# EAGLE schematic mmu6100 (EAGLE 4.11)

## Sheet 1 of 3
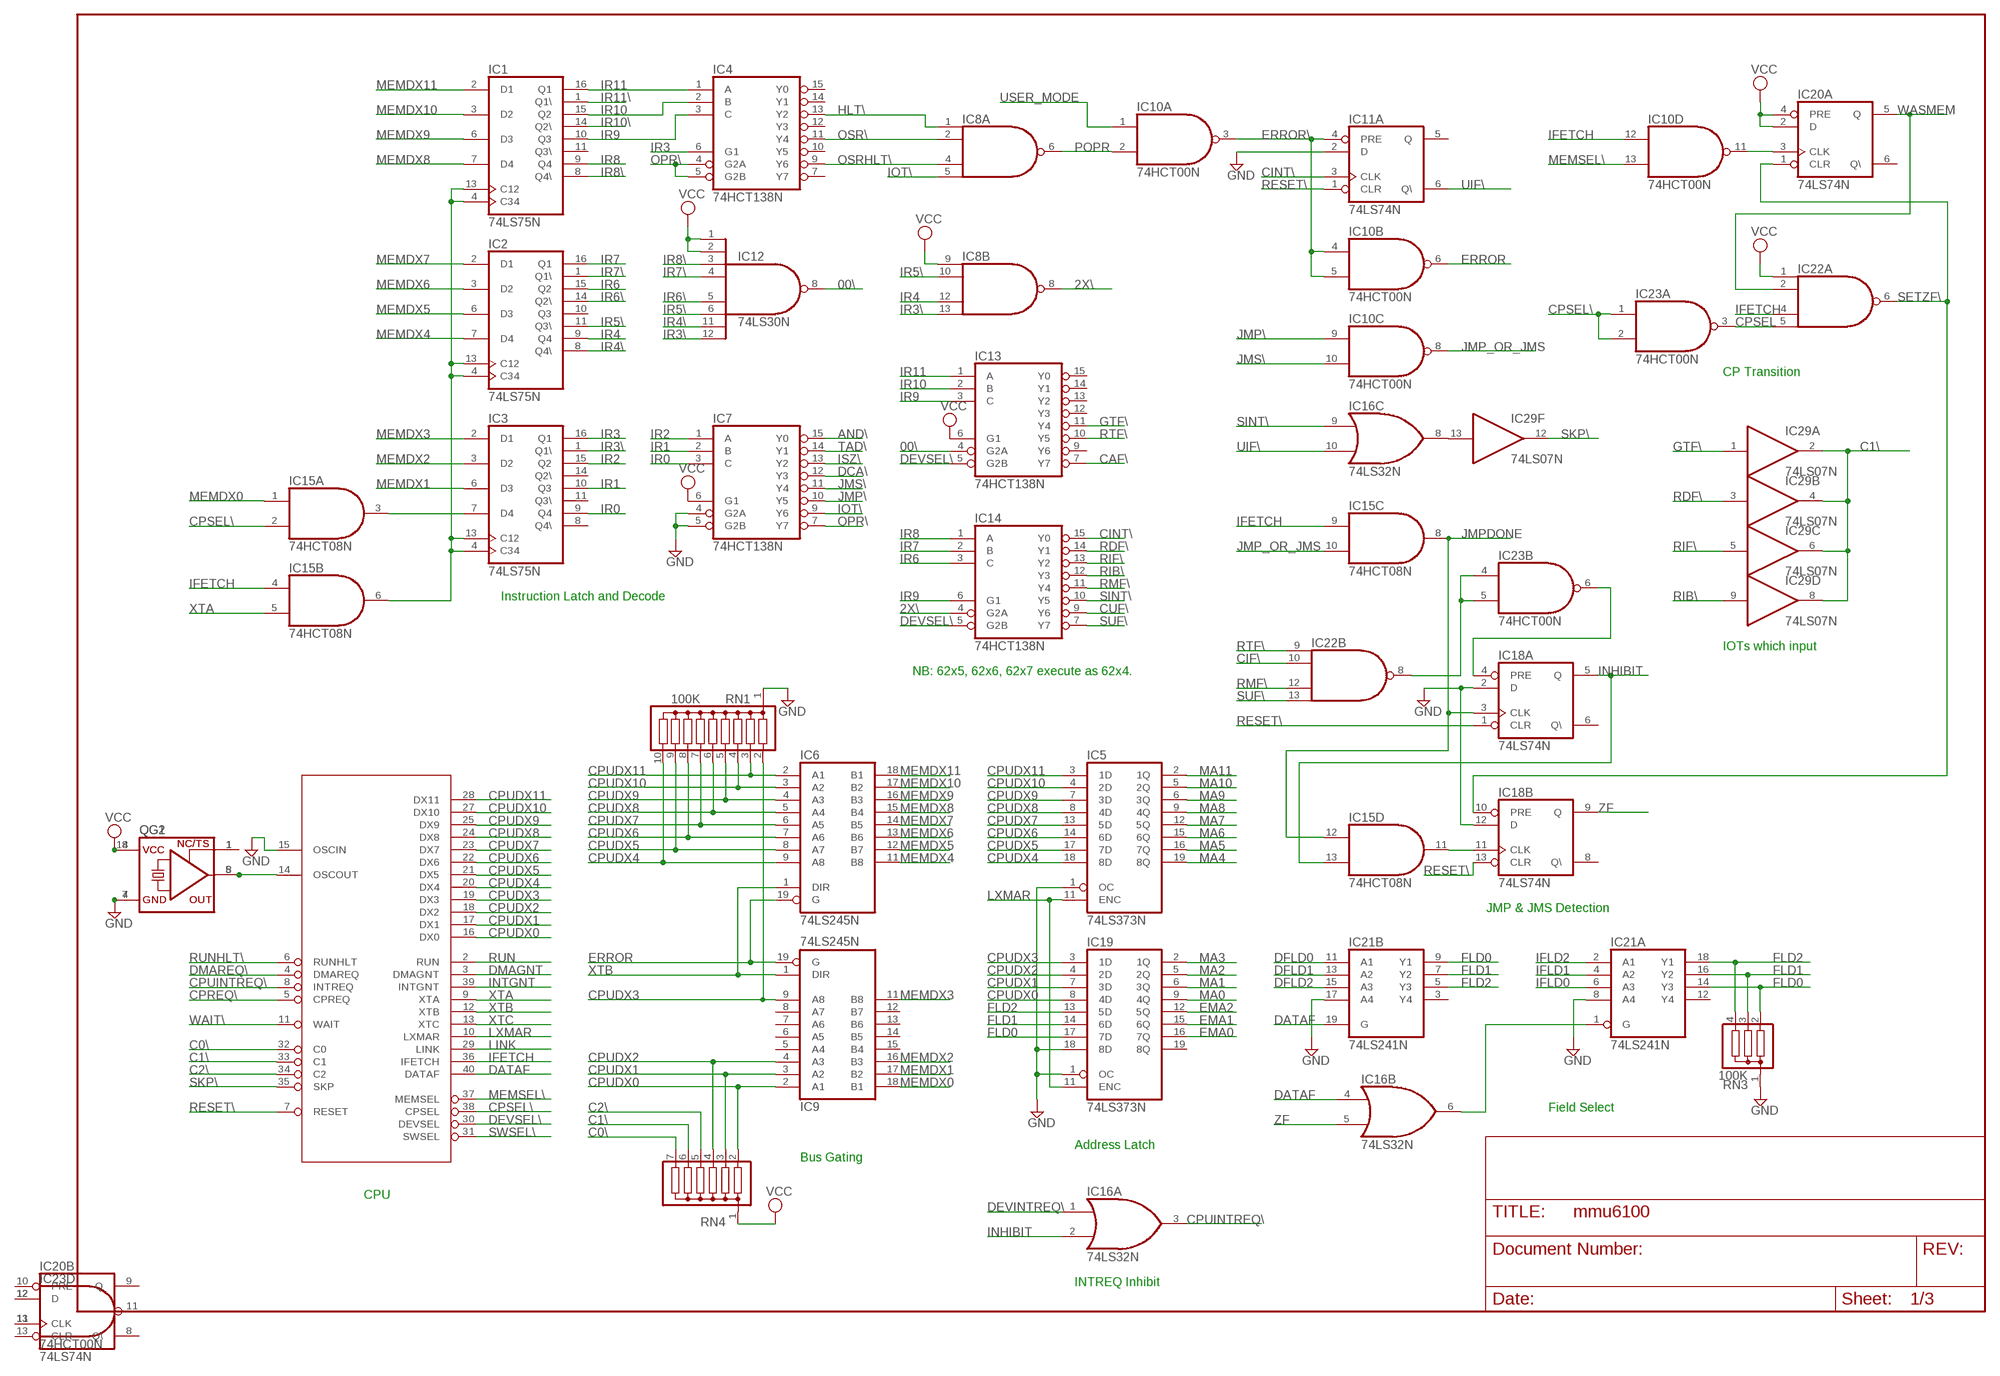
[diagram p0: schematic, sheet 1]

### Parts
CPU  IM6100  [DIL40]
IC1  74LS75N  [DIL16]
IC2  74LS75N  [DIL16]
IC3  74LS75N  [DIL16]
IC4  74HCT138N  [DIL16]
IC5  74LS373N  [DIL20]
IC6  74LS245N  [DIL20]
IC7  74HCT138N  [DIL16]
IC8  74LS20N  [DIL14]
IC9  74LS245N  [DIL20]
IC10  74HCT00N  [DIL14]
IC11  74LS74N  [DIL14]
IC12  74LS30N  [DIL14]
IC13  74HCT138N  [DIL16]
IC14  74HCT138N  [DIL16]
IC15  74HCT08N  [DIL14]
IC16  74LS32N  [DIL14]
IC18  74LS74N  [DIL14]
IC19  74LS373N  [DIL20]
IC20  74LS74N  [DIL14]
IC21  74LS241N  [DIL20]
IC22  74LS20N  [DIL14]
IC23  74HCT00N  [DIL14]
IC29  74LS07N  [DIL14]
QG1  XO-8  [DIL08S]
QG2  XO-14  [DIL14S]
RN1  100K  G09R  [SIL10]
RN3  100K  G03R  [SIL4]
RN4  G06R  [SIL7]

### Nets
00\: IC12.8(O) IC13.4(G2A)
2X\: IC8.8(B:O) IC14.4(G2A) ; also sheet 2
AND\: IC7.15(Y0) ; also sheet 3
C0\: CPU.32(C0) RN4.7 ; also sheet 3
C1\: CPU.33(C1) IC29.2(A:O) IC29.4(B:O) IC29.6(C:O) IC29.8(D:O) RN4.6 ; also sheet 3
C2\: CPU.34(C2) RN4.5 ; also sheet 3
CAF\: IC13.7(Y7) ; also sheet 2
CIF\: IC22.10(B:I1) ; also sheet 2
CINT\: IC11.3(A:CLK) IC14.15(Y0)
CPREQ\: CPU.5(CPREQ) ; also sheet 3
CPSEL: IC22.5(A:I3) IC23.3(A:O)
CPSEL\: CPU.38(CPSEL) IC15.2(A:I1) IC23.1(A:I0) IC23.2(A:I1)
CPUDX0: CPU.16(DX0) IC9.2(A1) IC19.8(4D) RN4.2 ; also sheet 2
CPUDX1: CPU.17(DX1) IC9.3(A2) IC19.7(3D) RN4.3 ; also sheet 2
CPUDX2: CPU.18(DX2) IC9.4(A3) IC19.4(2D) RN4.4 ; also sheet 2
CPUDX3: CPU.19(DX3) IC9.9(A8) IC19.3(1D) RN1.2 ; also sheet 2
CPUDX4: CPU.20(DX4) IC5.18(8D) IC6.9(A8) RN1.10 ; also sheet 2
CPUDX5: CPU.21(DX5) IC5.17(7D) IC6.8(A7) RN1.9 ; also sheet 2
CPUDX6: CPU.22(DX6) IC5.14(6D) IC6.7(A6) RN1.8 ; also sheet 2
CPUDX7: CPU.23(DX7) IC5.13(5D) IC6.6(A5) RN1.7 ; also sheet 2
CPUDX8: CPU.24(DX8) IC5.8(4D) IC6.5(A4) RN1.6 ; also sheet 2
CPUDX9: CPU.25(DX9) IC5.7(3D) IC6.4(A3) RN1.5 ; also sheet 2
CPUDX10: CPU.27(DX10) IC5.4(2D) IC6.3(A2) RN1.4 ; also sheet 2
CPUDX11: CPU.28(DX11) IC5.3(1D) IC6.2(A1) RN1.3 ; also sheet 2
CPUINTREQ\: CPU.8(INTREQ) IC16.3(A:O)
CUF\: IC14.9(Y6) ; also sheet 2
DATAF: CPU.40(DATAF) IC16.4(B:I0) IC21.19(B:G)
DCA\: IC7.12(Y3) ; also sheet 3
DEVINTREQ\: IC16.1(A:I0) ; also sheet 2,3
DEVSEL\: CPU.30(DEVSEL) IC13.5(G2B) IC14.5(G2B) ; also sheet 3
DFLD0: IC21.11(B:A1) ; also sheet 2
DFLD1: IC21.13(B:A2) ; also sheet 2
DFLD2: IC21.15(B:A3) ; also sheet 2
DMAGNT: CPU.3(DMAGNT) ; also sheet 3
DMAREQ\: CPU.4(DMAREQ) ; also sheet 3
EMA0: IC19.16(7Q) ; also sheet 3
EMA1: IC19.15(6Q) ; also sheet 3
EMA2: IC19.12(5Q) ; also sheet 3
ERROR: IC6.19(G) IC9.19(G) IC10.6(B:O)
ERROR\: IC10.3(A:O) IC10.4(B:I0) IC10.5(B:I1) IC11.4(A:PRE)
FLD0: IC19.17(7D) IC21.9(B:Y1) IC21.14(A:Y3) RN3.2
FLD1: IC19.14(6D) IC21.7(B:Y2) IC21.16(A:Y2) RN3.3
FLD2: IC19.13(5D) IC21.5(B:Y3) IC21.18(A:Y1) RN3.4
GND: CPU.15(OSCIN) IC5.1(OC) IC7.4(G2A) IC7.5(G2B) IC11.2(A:D) IC18.2(A:D) IC18.12(B:D) IC19.1(OC) IC19.18(8D) IC21.8(A:A4) IC21.17(B:A4) QG1.4(GND) QG2.7(GND) RN1.1 RN3.1 ; also sheet 2,3
GTF\: IC13.11(Y4) IC29.1(A:I) ; also sheet 2
HLT\: IC4.13(Y2) IC8.1(A:I0)
IFETCH: CPU.36(IFETCH) IC10.12(D:I0) IC15.4(B:I0) IC15.9(C:I0) IC22.4(A:I2)
IFLD0: IC21.6(A:A3) ; also sheet 2
IFLD1: IC21.4(A:A2) ; also sheet 2
IFLD2: IC21.2(A:A1) ; also sheet 2
INHIBIT: IC15.13(D:I1) IC16.2(A:I1) IC18.5(A:Q) ; also sheet 2
INTGNT: CPU.39(INTGNT) ; also sheet 2,3
IOT\: IC7.9(Y6) IC8.5(A:I3) ; also sheet 2
IR0: IC3.9(Q4) IC7.3(C)
IR1: IC3.10(Q3) IC7.2(B)
IR2: IC3.15(Q2) IC7.1(A)
IR3: IC3.16(Q1) IC4.6(G1)
IR3\: IC3.1(Q1\) IC8.13(B:I3) IC12.12(I7)
IR4: IC2.9(Q4) IC8.12(B:I2)
IR4\: IC2.8(Q4\) IC12.11(I6)
IR5\: IC2.11(Q3\) IC8.10(B:I1) IC12.6(I5)
IR6: IC2.15(Q2) IC14.3(C) ; also sheet 2
IR6\: IC2.14(Q2\) IC12.5(I4)
IR7: IC2.16(Q1) IC14.2(B) ; also sheet 2
IR7\: IC2.1(Q1\) IC12.4(I3)
IR8: IC1.9(Q4) IC14.1(A) ; also sheet 2
IR8\: IC1.8(Q4\) IC12.3(I2)
IR9: IC1.10(Q3) IC4.3(C) IC13.3(C) IC14.6(G1) ; also sheet 2
IR10: IC1.15(Q2) IC4.2(B) IC13.2(B)
IR10\: IC1.14(Q2\) ; also sheet 2
IR11: IC1.16(Q1) IC4.1(A) IC13.1(A)
IR11\: IC1.1(Q1\) ; also sheet 2
ISZ\: IC7.13(Y2) ; also sheet 3
JMP\: IC7.10(Y5) IC10.9(C:I0)
JMP_OR_JMS: IC10.8(C:O) IC15.10(C:I1)
JMPDONE: IC15.8(C:O) IC15.12(D:I0) IC18.3(A:CLK) ; also sheet 2
JMS\: IC7.11(Y4) IC10.10(C:I1)
LINK: CPU.29(LINK) ; also sheet 3
LXMAR: CPU.10(LXMAR) IC5.11(ENC) IC19.11(ENC) ; also sheet 2,3
MA0: IC19.9(4Q) ; also sheet 3
MA1: IC19.6(3Q) ; also sheet 3
MA2: IC19.5(2Q) ; also sheet 3
MA3: IC19.2(1Q) ; also sheet 3
MA4: IC5.19(8Q) ; also sheet 3
MA5: IC5.16(7Q) ; also sheet 3
MA6: IC5.15(6Q) ; also sheet 3
MA7: IC5.12(5Q) ; also sheet 3
MA8: IC5.9(4Q) ; also sheet 3
MA9: IC5.6(3Q) ; also sheet 3
MA10: IC5.5(2Q) ; also sheet 3
MA11: IC5.2(1Q) ; also sheet 3
MEMDX0: IC9.18(B1) IC15.1(A:I0) ; also sheet 3
MEMDX1: IC3.6(D3) IC9.17(B2) ; also sheet 3
MEMDX2: IC3.3(D2) IC9.16(B3) ; also sheet 3
MEMDX3: IC3.2(D1) IC9.11(B8) ; also sheet 3
MEMDX4: IC2.7(D4) IC6.11(B8) ; also sheet 3
MEMDX5: IC2.6(D3) IC6.12(B7) ; also sheet 3
MEMDX6: IC2.3(D2) IC6.13(B6) ; also sheet 3
MEMDX7: IC2.2(D1) IC6.14(B5) ; also sheet 3
MEMDX8: IC1.7(D4) IC6.15(B4) ; also sheet 3
MEMDX9: IC1.6(D3) IC6.16(B3) ; also sheet 3
MEMDX10: IC1.3(D2) IC6.17(B2) ; also sheet 3
MEMDX11: IC1.2(D1) IC6.18(B1) ; also sheet 3
MEMSEL\: CPU.37(MEMSEL) IC10.13(D:I1) ; also sheet 3
N$2: QG1.1(TS) QG2.1(TS)
N$3: IC1.4(C34) IC1.13(C12) IC2.4(C34) IC2.13(C12) IC3.4(C34) IC3.13(C12) IC15.6(B:O)
N$5: IC15.11(D:O) IC18.11(B:CLK)
N$6: IC10.11(D:O) IC20.3(A:CLK)
N$8: IC16.6(B:O) IC21.1(A:G)
N$15: IC3.7(D4) IC15.3(A:O)
N$23: IC16.8(C:O) IC29.13(F:I)
N$29: IC22.8(B:O) IC23.4(B:I0) IC23.5(B:I1)
N$30: IC18.4(A:PRE) IC23.6(B:O)
OPR\: IC4.4(G2A) IC4.5(G2B) IC7.7(Y7)
OSCOUT: CPU.14(OSCOUT) QG1.5(OUT) QG2.8(OUT)
OSR\: IC4.11(Y4) IC8.2(A:I1)
OSRHLT\: IC4.9(Y6) IC8.4(A:I2)
POPR: IC8.6(A:O) IC10.2(A:I1)
RDF\: IC14.14(Y1) IC29.3(B:I) ; also sheet 2
RESET\: CPU.7(RESET) IC11.1(A:CLR) IC18.1(A:CLR) IC18.13(B:CLR) ; also sheet 2,3
RIB\: IC14.12(Y3) IC29.9(D:I) ; also sheet 2
RIF\: IC14.13(Y2) IC29.5(C:I) ; also sheet 2
RMF\: IC14.11(Y4) IC22.12(B:I2) ; also sheet 2
RTF\: IC13.10(Y5) IC22.9(B:I0) ; also sheet 2
RUN: CPU.2(RUN) ; also sheet 3
RUNHLT\: CPU.6(RUNHLT) ; also sheet 3
SETZF\: IC18.10(B:PRE) IC20.1(A:CLR) IC22.6(A:O)
SINT\: IC14.10(Y5) IC16.9(C:I0)
SKP\: CPU.35(SKP) IC29.12(F:O) ; also sheet 3
SUF\: IC14.7(Y7) IC22.13(B:I3) ; also sheet 2
SWSEL\: CPU.31(SWSEL) ; also sheet 3
TAD\: IC7.14(Y1) ; also sheet 3
UIF\: IC11.6(A:Q\) IC16.10(C:I1)
USER_MODE: IC10.1(A:I0) ; also sheet 2
VCC: IC7.6(G1) IC8.9(B:I0) IC12.1(I0) IC12.2(I1) IC13.6(G1) IC20.2(A:D) IC20.4(A:PRE) IC22.1(A:I0) QG1.8(VCC) QG2.14(VCC) RN4.1 ; also sheet 2,3
WAIT\: CPU.11(WAIT) ; also sheet 3
WASMEM: IC20.5(A:Q) IC22.2(A:I1)
XTA: CPU.9(XTA) IC15.5(B:I1) ; also sheet 2,3
XTB: CPU.12(XTB) IC6.1(DIR) IC9.1(DIR) ; also sheet 2,3
XTC: CPU.13(XTC) ; also sheet 3
ZF: IC16.5(B:I1) IC18.9(B:Q)
Unconnected: IC1.11(Q3\) IC2.10(Q3) IC3.8(Q4\) IC3.11(Q3\) IC3.14(Q2\) IC4.7(Y7) IC4.10(Y5) IC4.12(Y3) IC4.14(Y1) IC4.15(Y0) IC9.5(A4) IC9.6(A5) IC9.7(A6) IC9.8(A7) IC9.12(B7) IC9.13(B6) IC9.14(B5) IC9.15(B4) IC13.9(Y6) IC13.12(Y3) IC13.13(Y2) IC13.14(Y1) IC13.15(Y0) IC18.6(A:Q\) IC18.8(B:Q\) IC19.19(8Q) IC21.3(B:Y4) IC21.12(A:Y4)

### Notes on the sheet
- CP Transition
- Instruction Latch and Decode
- IOTs which input
- NB: 62x5, 62x6, 62x7 execute as 62x4.
- JMP & JMS Detection
- Field Select
- Address Latch
- Bus Gating
- CPU
- INTREQ Inhibit

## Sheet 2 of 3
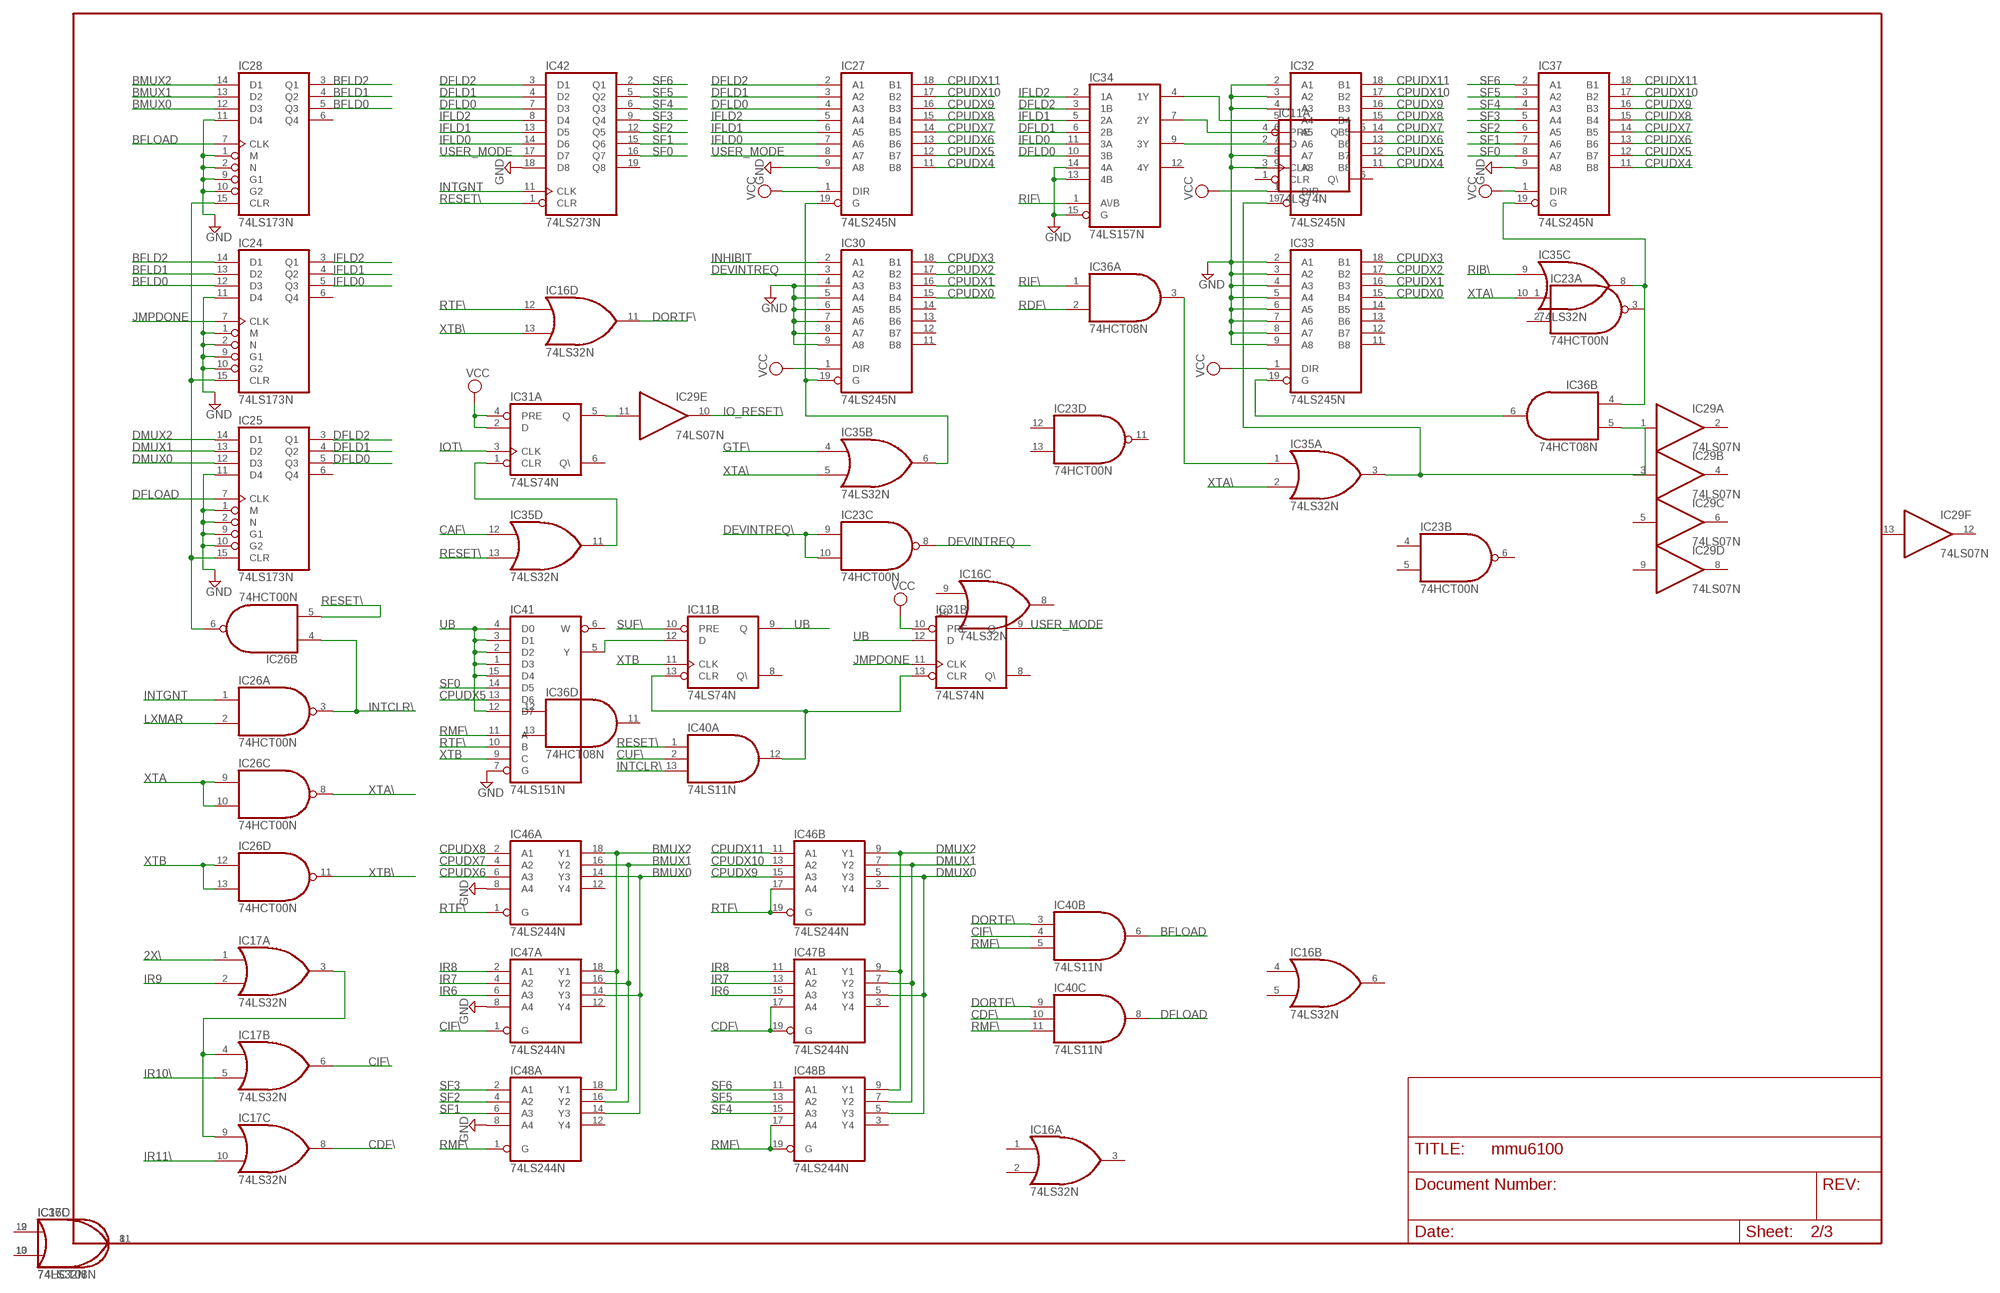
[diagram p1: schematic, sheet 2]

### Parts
IC17  74LS32N  [DIL14]
IC24  74LS173N  [DIL16]
IC25  74LS173N  [DIL16]
IC26  74HCT00N  [DIL14]
IC27  74LS245N  [DIL20]
IC28  74LS173N  [DIL16]
IC30  74LS245N  [DIL20]
IC31  74LS74N  [DIL14]
IC32  74LS245N  [DIL20]
IC33  74LS245N  [DIL20]
IC34  74LS157N  [DIL16]
IC35  74LS32N  [DIL14]
IC36  74HCT08N  [DIL14]
IC37  74LS245N  [DIL20]
IC40  74LS11N  [DIL14]
IC41  74LS151N  [DIL16]
IC42  74LS273N  [DIL20]
IC46  74LS244N  [DIL20]
IC47  74LS244N  [DIL20]
IC48  74LS244N  [DIL20]

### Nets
2X\: IC17.1(A:I0) ; also sheet 1
BFLD0: IC24.12(D3) IC28.5(Q3)
BFLD1: IC24.13(D2) IC28.4(Q2)
BFLD2: IC24.14(D1) IC28.3(Q1)
BFLOAD: IC28.7(CLK) IC40.6(B:O)
BMUX0: IC28.12(D3) IC46.14(A:Y3) IC47.14(A:Y3) IC48.14(A:Y3)
BMUX1: IC28.13(D2) IC46.16(A:Y2) IC47.16(A:Y2) IC48.16(A:Y2)
BMUX2: IC28.14(D1) IC46.18(A:Y1) IC47.18(A:Y1) IC48.18(A:Y1)
CAF\: IC35.12(D:I0) ; also sheet 1
CDF\: IC17.8(C:O) IC40.10(C:I1) IC47.17(B:A4) IC47.19(B:G)
CIF\: IC17.6(B:O) IC40.4(B:I1) IC47.1(A:G) ; also sheet 1
CPUDX0: IC30.15(B4) IC33.15(B4) ; also sheet 1
CPUDX1: IC30.16(B3) IC33.16(B3) ; also sheet 1
CPUDX2: IC30.17(B2) IC33.17(B2) ; also sheet 1
CPUDX3: IC30.18(B1) IC33.18(B1) ; also sheet 1
CPUDX4: IC27.11(B8) IC32.11(B8) IC37.11(B8) ; also sheet 1
CPUDX5: IC27.12(B7) IC32.12(B7) IC37.12(B7) IC41.13(D6) ; also sheet 1
CPUDX6: IC27.13(B6) IC32.13(B6) IC37.13(B6) IC46.6(A:A3) ; also sheet 1
CPUDX7: IC27.14(B5) IC32.14(B5) IC37.14(B5) IC46.4(A:A2) ; also sheet 1
CPUDX8: IC27.15(B4) IC32.15(B4) IC37.15(B4) IC46.2(A:A1) ; also sheet 1
CPUDX9: IC27.16(B3) IC32.16(B3) IC37.16(B3) IC46.15(B:A3) ; also sheet 1
CPUDX10: IC27.17(B2) IC32.17(B2) IC37.17(B2) IC46.13(B:A2) ; also sheet 1
CPUDX11: IC27.18(B1) IC32.18(B1) IC37.18(B1) IC46.11(B:A1) ; also sheet 1
CUF\: IC40.2(A:I1) ; also sheet 1
DEVINTREQ: IC23.8(C:O) IC30.3(A2)
DEVINTREQ\: IC23.9(C:I0) IC23.10(C:I1) ; also sheet 1,3
DFLD0: IC25.5(Q3) IC27.4(A3) IC34.10(3B) IC42.7(D3) ; also sheet 1
DFLD1: IC25.4(Q2) IC27.3(A2) IC34.6(2B) IC42.4(D2) ; also sheet 1
DFLD2: IC25.3(Q1) IC27.2(A1) IC34.3(1B) IC42.3(D1) ; also sheet 1
DFLOAD: IC25.7(CLK) IC40.8(C:O)
DMUX0: IC25.12(D3) IC46.5(B:Y3) IC47.5(B:Y3) IC48.5(B:Y3)
DMUX1: IC25.13(D2) IC46.7(B:Y2) IC47.7(B:Y2) IC48.7(B:Y2)
DMUX2: IC25.14(D1) IC46.9(B:Y1) IC47.9(B:Y1) IC48.9(B:Y1)
DORTF\: IC16.11(D:O) IC40.3(B:I0) IC40.9(C:I0)
GND: IC24.1(M) IC24.2(N) IC24.9(G1) IC24.10(G2) IC24.11(D4) IC25.1(M) IC25.2(N) IC25.9(G1) IC25.10(G2) IC25.11(D4) IC27.9(A8) IC28.1(M) IC28.2(N) IC28.9(G1) IC28.10(G2) IC28.11(D4) IC30.4(A3) IC30.5(A4) IC30.6(A5) IC30.7(A6) IC30.8(A7) IC30.9(A8) IC32.2(A1) IC32.3(A2) IC32.4(A3) IC32.8(A7) IC32.9(A8) IC33.2(A1) IC33.3(A2) IC33.4(A3) IC33.5(A4) IC33.6(A5) IC33.7(A6) IC33.8(A7) IC33.9(A8) IC34.13(4B) IC34.14(4A) IC34.15(G) IC37.9(A8) IC41.7(G) IC42.18(D8) IC46.8(A:A4) IC47.8(A:A4) IC48.8(A:A4) ; also sheet 1,3
GTF\: IC35.4(B:I0) ; also sheet 1
IFLD0: IC24.5(Q3) IC27.7(A6) IC34.11(3A) IC42.14(D6) ; also sheet 1
IFLD1: IC24.4(Q2) IC27.6(A5) IC34.5(2A) IC42.13(D5) ; also sheet 1
IFLD2: IC24.3(Q1) IC27.5(A4) IC34.2(1A) IC42.8(D4) ; also sheet 1
INHIBIT: IC30.2(A1) ; also sheet 1
INTCLR: IC24.15(CLR) IC25.15(CLR) IC26.6(B:O) IC28.15(CLR)
INTCLR\: IC26.3(A:O) IC26.4(B:I0) IC40.13(A:I2)
INTGNT: IC26.1(A:I0) IC42.11(CLK) ; also sheet 1,3
IO_RESET\: IC29.10(E:O) ; also sheet 3
IOT\: IC31.3(A:CLK) ; also sheet 1
IR6: IC47.6(A:A3) IC47.15(B:A3) ; also sheet 1
IR7: IC47.4(A:A2) IC47.13(B:A2) ; also sheet 1
IR8: IC47.2(A:A1) IC47.11(B:A1) ; also sheet 1
IR9: IC17.2(A:I1) ; also sheet 1
IR10\: IC17.5(B:I1) ; also sheet 1
IR11\: IC17.10(C:I1) ; also sheet 1
JMPDONE: IC24.7(CLK) IC31.11(B:CLK) ; also sheet 1
LXMAR: IC26.2(A:I1) ; also sheet 1,3
N$4: IC27.19(G) IC30.19(G) IC35.6(B:O)
N$7: IC29.11(E:I) IC31.5(A:Q)
N$9: IC32.19(G) IC35.3(A:O) IC36.5(B:I1)
N$12: IC35.8(C:O) IC36.4(B:I0) IC37.19(G)
N$14: IC32.5(A4) IC34.4(1Y)
N$19: IC32.6(A5) IC34.7(2Y)
N$22: IC32.7(A6) IC34.9(3Y)
N$24: IC35.1(A:I0) IC36.3(A:O)
N$25: IC33.19(G) IC36.6(B:O)
N$26: IC11.13(B:CLR) IC31.13(B:CLR) IC40.12(A:O)
N$27: IC11.12(B:D) IC41.5(Y)
N$28: IC31.1(A:CLR) IC35.11(D:O)
N$33: IC17.3(A:O) IC17.4(B:I0) IC17.9(C:I0)
RDF\: IC36.2(A:I1) ; also sheet 1
RESET\: IC26.5(B:I1) IC35.13(D:I1) IC40.1(A:I0) IC42.1(CLR) ; also sheet 1,3
RIB\: IC35.9(C:I0) ; also sheet 1
RIF\: IC34.1(A\/B) IC36.1(A:I0) ; also sheet 1
RMF\: IC40.5(B:I2) IC40.11(C:I2) IC41.11(A) IC48.1(A:G) IC48.17(B:A4) IC48.19(B:G) ; also sheet 1
RTF\: IC16.12(D:I0) IC41.10(B) IC46.1(A:G) IC46.17(B:A4) IC46.19(B:G) ; also sheet 1
SF0: IC37.8(A7) IC41.14(D5) IC42.16(Q7)
SF1: IC37.7(A6) IC42.15(Q6) IC48.6(A:A3)
SF2: IC37.6(A5) IC42.12(Q5) IC48.4(A:A2)
SF3: IC37.5(A4) IC42.9(Q4) IC48.2(A:A1)
SF4: IC37.4(A3) IC42.6(Q3) IC48.15(B:A3)
SF5: IC37.3(A2) IC42.5(Q2) IC48.13(B:A2)
SF6: IC37.2(A1) IC42.2(Q1) IC48.11(B:A1)
SUF\: IC11.10(B:PRE) ; also sheet 1
UB: IC11.9(B:Q) IC31.12(B:D) IC41.1(D3) IC41.2(D2) IC41.3(D1) IC41.4(D0) IC41.12(D7) IC41.15(D4)
USER_MODE: IC27.8(A7) IC31.9(B:Q) IC42.17(D7) ; also sheet 1
VCC: IC27.1(DIR) IC30.1(DIR) IC31.2(A:D) IC31.4(A:PRE) IC31.10(B:PRE) IC32.1(DIR) IC33.1(DIR) IC37.1(DIR) ; also sheet 1,3
XTA: IC26.9(C:I0) IC26.10(C:I1) ; also sheet 1,3
XTA\: IC26.8(C:O) IC35.2(A:I1) IC35.5(B:I1) IC35.10(C:I1) ; also sheet 3
XTB: IC11.11(B:CLK) IC26.12(D:I0) IC26.13(D:I1) IC41.9(C) ; also sheet 1,3
XTB\: IC16.13(D:I1) IC26.11(D:O) ; also sheet 3
Unconnected: IC11.5(A:Q) IC11.8(B:Q\) IC24.6(Q4) IC25.6(Q4) IC28.6(Q4) IC30.11(B8) IC30.12(B7) IC30.13(B6) IC30.14(B5) IC31.6(A:Q\) IC31.8(B:Q\) IC33.11(B8) IC33.12(B7) IC33.13(B6) IC33.14(B5) IC34.12(4Y) IC41.6(W) IC42.19(Q8) IC46.3(B:Y4) IC46.12(A:Y4) IC47.3(B:Y4) IC47.12(A:Y4) IC48.3(B:Y4) IC48.12(A:Y4)

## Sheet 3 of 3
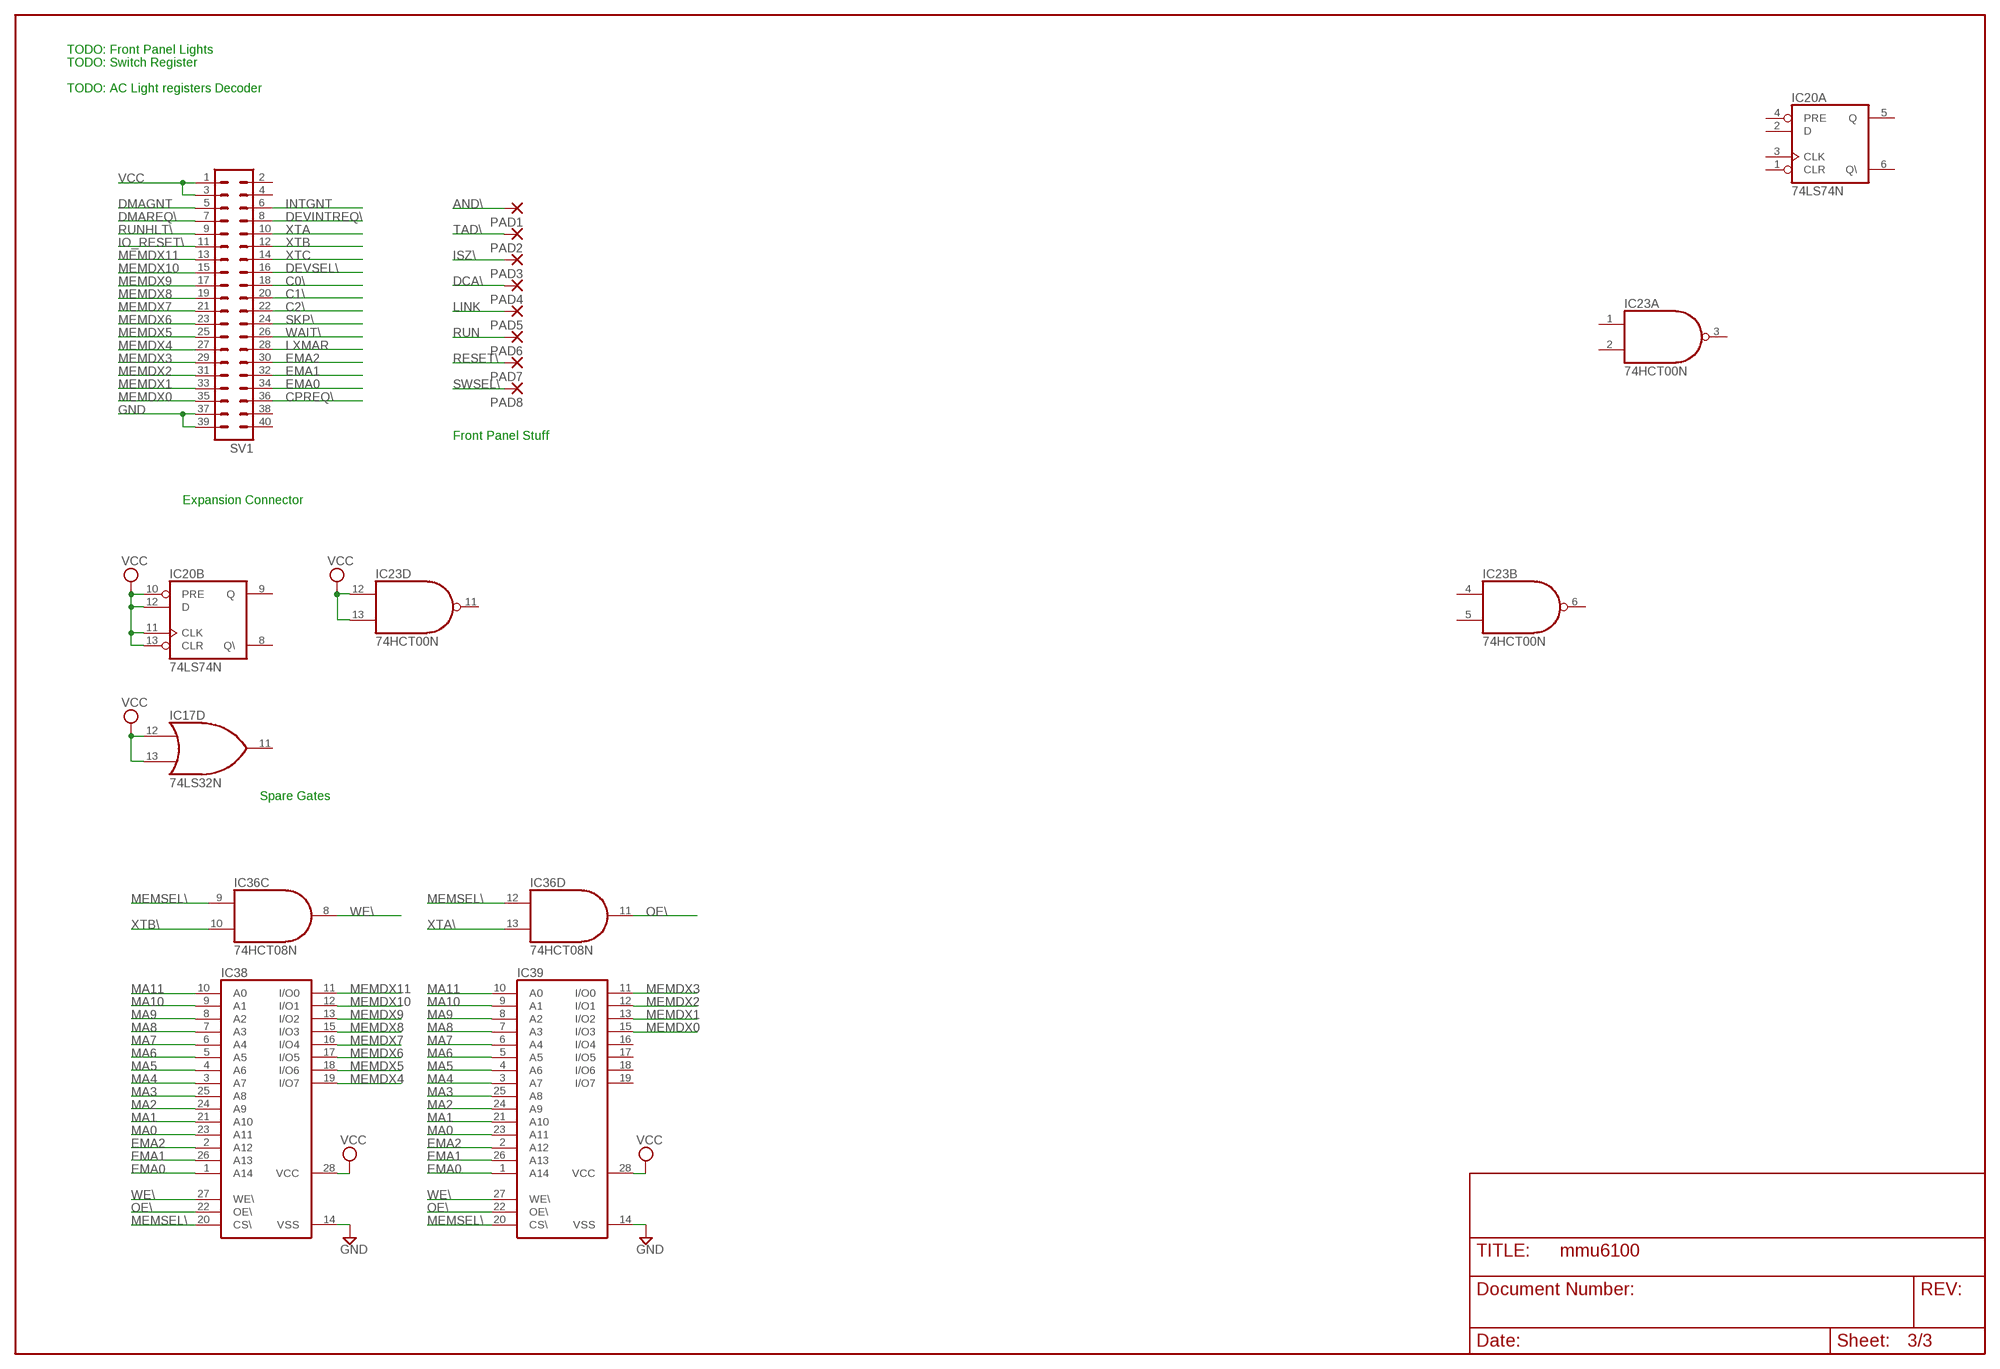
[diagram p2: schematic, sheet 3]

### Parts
IC38  62256P  [DIL28-6]
IC39  62256P  [DIL28-6]
PAD1  2,15/1,0  [2,15/1,0]
PAD2  2,15/1,0  [2,15/1,0]
PAD3  2,15/1,0  [2,15/1,0]
PAD4  2,15/1,0  [2,15/1,0]
PAD5  2,15/1,0  [2,15/1,0]
PAD6  2,15/1,0  [2,15/1,0]
PAD7  2,15/1,0  [2,15/1,0]
PAD8  2,15/1,0  [2,15/1,0]
SV1  MA20-2  [MA20-2]

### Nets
AND\: PAD1.1(P) ; also sheet 1
C0\: SV1.18 ; also sheet 1
C1\: SV1.20 ; also sheet 1
C2\: SV1.22 ; also sheet 1
CPREQ\: SV1.36 ; also sheet 1
DCA\: PAD4.1(P) ; also sheet 1
DEVINTREQ\: SV1.8 ; also sheet 1,2
DEVSEL\: SV1.16 ; also sheet 1
DMAGNT: SV1.5 ; also sheet 1
DMAREQ\: SV1.7 ; also sheet 1
EMA0: IC38.1(A14) IC39.1(A14) SV1.34 ; also sheet 1
EMA1: IC38.26(A13) IC39.26(A13) SV1.32 ; also sheet 1
EMA2: IC38.2(A12) IC39.2(A12) SV1.30 ; also sheet 1
GND: IC38.14(VSS) IC39.14(VSS) SV1.37 SV1.39 ; also sheet 1,2
INTGNT: SV1.6 ; also sheet 1,2
IO_RESET\: SV1.11 ; also sheet 2
ISZ\: PAD3.1(P) ; also sheet 1
LINK: PAD5.1(P) ; also sheet 1
LXMAR: SV1.28 ; also sheet 1,2
MA0: IC38.23(A11) IC39.23(A11) ; also sheet 1
MA1: IC38.21(A10) IC39.21(A10) ; also sheet 1
MA2: IC38.24(A9) IC39.24(A9) ; also sheet 1
MA3: IC38.25(A8) IC39.25(A8) ; also sheet 1
MA4: IC38.3(A7) IC39.3(A7) ; also sheet 1
MA5: IC38.4(A6) IC39.4(A6) ; also sheet 1
MA6: IC38.5(A5) IC39.5(A5) ; also sheet 1
MA7: IC38.6(A4) IC39.6(A4) ; also sheet 1
MA8: IC38.7(A3) IC39.7(A3) ; also sheet 1
MA9: IC38.8(A2) IC39.8(A2) ; also sheet 1
MA10: IC38.9(A1) IC39.9(A1) ; also sheet 1
MA11: IC38.10(A0) IC39.10(A0) ; also sheet 1
MEMDX0: IC39.15(I/O3) SV1.35 ; also sheet 1
MEMDX1: IC39.13(I/O2) SV1.33 ; also sheet 1
MEMDX2: IC39.12(I/O1) SV1.31 ; also sheet 1
MEMDX3: IC39.11(I/O0) SV1.29 ; also sheet 1
MEMDX4: IC38.19(I/O7) SV1.27 ; also sheet 1
MEMDX5: IC38.18(I/O6) SV1.25 ; also sheet 1
MEMDX6: IC38.17(I/O5) SV1.23 ; also sheet 1
MEMDX7: IC38.16(I/O4) SV1.21 ; also sheet 1
MEMDX8: IC38.15(I/O3) SV1.19 ; also sheet 1
MEMDX9: IC38.13(I/O2) SV1.17 ; also sheet 1
MEMDX10: IC38.12(I/O1) SV1.15 ; also sheet 1
MEMDX11: IC38.11(I/O0) SV1.13 ; also sheet 1
MEMSEL\: IC36.9(C:I0) IC36.12(D:I0) IC38.20(CS\) IC39.20(CS\) ; also sheet 1
OE\: IC36.11(D:O) IC38.22(OE\) IC39.22(OE\)
RESET\: PAD7.1(P) ; also sheet 1,2
RUN: PAD6.1(P) ; also sheet 1
RUNHLT\: SV1.9 ; also sheet 1
SKP\: SV1.24 ; also sheet 1
SWSEL\: PAD8.1(P) ; also sheet 1
TAD\: PAD2.1(P) ; also sheet 1
VCC: IC17.12(D:I0) IC17.13(D:I1) IC20.10(B:PRE) IC20.11(B:CLK) IC20.12(B:D) IC20.13(B:CLR) IC23.12(D:I0) IC23.13(D:I1) IC38.28(VCC) IC39.28(VCC) SV1.1 SV1.3 ; also sheet 1,2
WAIT\: SV1.26 ; also sheet 1
WE\: IC36.8(C:O) IC38.27(WE\) IC39.27(WE\)
XTA: SV1.10 ; also sheet 1,2
XTA\: IC36.13(D:I1) ; also sheet 2
XTB: SV1.12 ; also sheet 1,2
XTB\: IC36.10(C:I1) ; also sheet 2
XTC: SV1.14 ; also sheet 1
Unconnected: IC17.11(D:O) IC20.6(A:Q\) IC20.8(B:Q\) IC20.9(B:Q) IC23.11(D:O) IC39.16(I/O4) IC39.17(I/O5) IC39.18(I/O6) IC39.19(I/O7) SV1.2 SV1.4 SV1.38 SV1.40

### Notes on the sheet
- TODO: Front Panel Lights
- TODO: Switch Register
- TODO: AC Light registers Decoder
- Front Panel Stuff
- Expansion Connector
- Spare Gates

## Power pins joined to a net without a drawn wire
GND: CPU.26(GND) IC1.12(GND) IC2.12(GND) IC3.12(GND) IC4.8(GND) IC5.10(GND) IC6.10(GND) IC7.8(GND) IC8.7(P:GND) IC9.10(GND) IC10.7(P:GND) IC11.7(P:GND) IC12.7(GND) IC13.8(GND) IC14.8(GND) IC15.7(P:GND) IC16.7(P:GND) IC17.7(P:GND) IC18.7(P:GND) IC19.10(GND) IC20.7(P:GND) IC21.10(P:GND) IC22.7(P:GND) IC23.7(P:GND) IC24.8(GND) IC25.8(GND) IC26.7(P:GND) IC27.10(GND) IC28.8(GND) IC29.7(P:GND) IC30.10(GND) IC31.7(P:GND) IC32.10(GND) IC33.10(GND) IC34.8(GND) IC35.7(P:GND) IC36.7(P:GND) IC37.10(GND) IC40.7(P:GND) IC41.8(GND) IC42.10(GND) IC46.10(P:GND) IC47.10(P:GND) IC48.10(P:GND)
VCC: CPU.1(VCC) IC1.5(VCC) IC2.5(VCC) IC3.5(VCC) IC4.16(VCC) IC5.20(VCC) IC6.20(VCC) IC7.16(VCC) IC8.14(P:VCC) IC9.20(VCC) IC10.14(P:VCC) IC11.14(P:VCC) IC12.14(VCC) IC13.16(VCC) IC14.16(VCC) IC15.14(P:VCC) IC16.14(P:VCC) IC17.14(P:VCC) IC18.14(P:VCC) IC19.20(VCC) IC20.14(P:VCC) IC21.20(P:VCC) IC22.14(P:VCC) IC23.14(P:VCC) IC24.16(VCC) IC25.16(VCC) IC26.14(P:VCC) IC27.20(VCC) IC28.16(VCC) IC29.14(P:VCC) IC30.20(VCC) IC31.14(P:VCC) IC32.20(VCC) IC33.20(VCC) IC34.16(VCC) IC35.14(P:VCC) IC36.14(P:VCC) IC37.20(VCC) IC40.14(P:VCC) IC41.16(VCC) IC42.20(VCC) IC46.20(P:VCC) IC47.20(P:VCC) IC48.20(P:VCC)

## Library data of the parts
CPU = dec-con:IM6100: IM6100 PDP-8 on a chip.
IC1-IC3 = 74xx-jameco:74*75: 4-bit bistable LATCH
IC4 IC7 IC13 IC14 = 74xx-jameco:74*138: 3-line to 8-line DECODER/DEMULTIPLEXER
IC5 IC19 = 74xx-jameco:74*373: Octal D type transparent LATCH
IC6 IC9 IC27 IC30 IC32 IC33 IC37 = 74xx-jameco:74*245: Octal BUS TRANSCEIVER, 3-state
IC8 IC22 = 74xx-jameco:74*20: Dual 4-input NAND gate
IC10 IC23 IC26 = 74xx-jameco:74*00: Quad 2-input NAND gate
IC11 IC18 IC20 IC31 = 74xx-jameco:74*74: Dual D type positive edge triggered FLIP FLOP, preset and clear
IC12 = 74xx-jameco:74*30: 8-input NAND gate
IC15 IC36 = 74xx-jameco:74*08: Quad 2-input AND gate
IC16 IC17 IC35 = 74xx-jameco:74*32: Quad 2-input OR gate
IC21 = 74xx-jameco:74*241: Octal BUFFER and LINE DRIVER, 3-state
IC24 IC25 IC28 = 74xx-jameco:74*173: 4-bit D type REGISTER, 3-state
IC29 = 74xx-jameco:74*07: Hex BUFFER, open collector high-voltage output
IC34 = 74xx-jameco:74*157: Quadruple 2-line to 1-line data SELECTOR/MULTIPLEXER
IC38 IC39 = memory-hitachi:62256P: MEMORY
IC40 = 74xx-jameco:74*11: Triple 3-input AND gate
IC41 = 74xx-jameco:74*151: Data SELECTOR/MULTIPLEXER
IC42 = 74xx-jameco:74*273: Octal D type FLIP FLOP, clear
IC46-IC48 = 74xx-jameco:74*244: Octal BUFFER and LINE DRIVER, 3-state
PAD1-PAD8 = wirepad:2,15/1,0: THROUGH-HOLE PAD
QG1 QG2 = crystal:XO-: CRYSTAL
RN1 = resistor-sil:G09R: SIL RESISTOR
RN3 = resistor-sil:G03R: SIL RESISTOR
RN4 = resistor-sil:G06R: SIL RESISTOR
SV1 = con-lstb:MA20-2: PIN HEADER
